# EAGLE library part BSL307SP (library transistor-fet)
OptiMOS(R)-P Small-Signal-Transistor P-Channel, Enhancement mode, Logic Level ID -5.5 A Source: http://www.infineon.com/upload/Document/BSL307SP_Rev%201.2.pdf
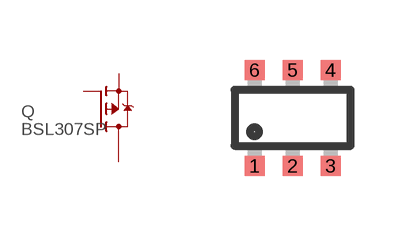
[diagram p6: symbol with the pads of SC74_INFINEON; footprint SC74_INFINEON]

Designator prefix Q

## BSL307SP  [SC74_INFINEON]
1  D  pas
2  D  pas
3  G  pas
4  S  pas
5  D  pas
6  D  pas

## Footprint SC74_INFINEON (pad centres in mm)
Small Outline Transistor; 6 leads Reflow soldering INFINEON, www.infineon.com/cmc_upload/0/000/010/257/eh_db_5b.pdf
smd 0.5 x 0.5: 1 -0.95,-1.2; 2 0,-1.2; 3 0.95,-1.2; 4 0.95,1.2; 5 0,1.2; 6 -0.95,1.2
